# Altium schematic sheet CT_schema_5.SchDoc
size 297 x 173 mm
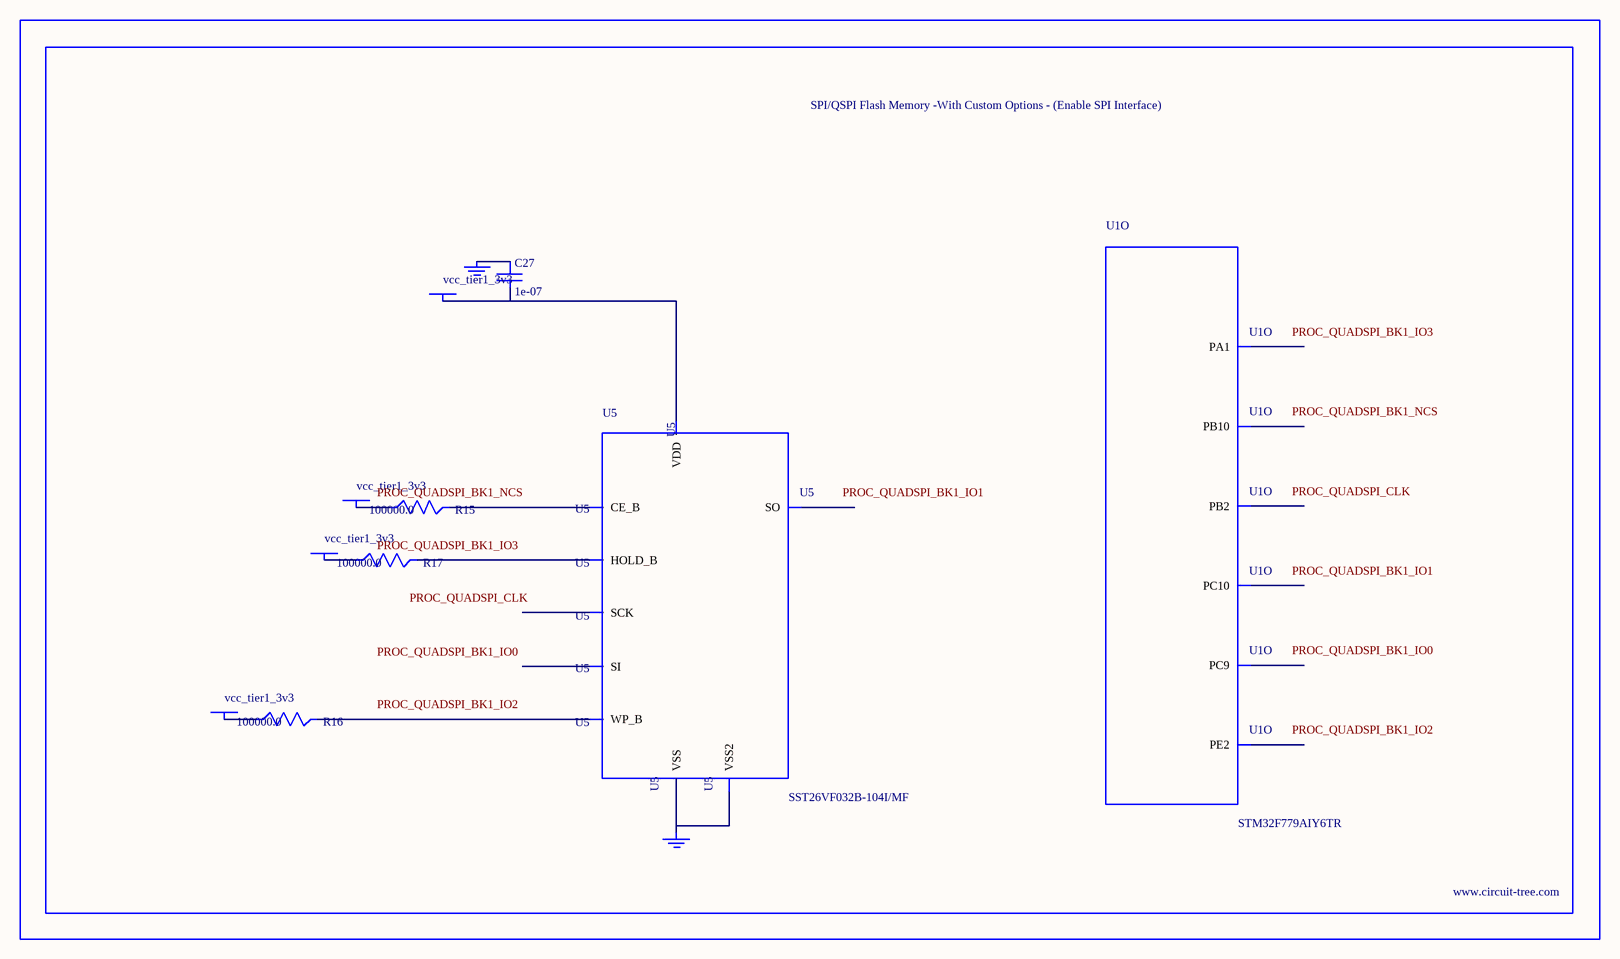
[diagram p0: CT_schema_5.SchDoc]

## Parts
BORDER4  (no value)
C27  1e-07  [C0402]
GND_INSTANCE_4_0  (no value)
GND_INSTANCE_4_1  (no value)
POWER_INSTANCE_4_0  vcc_tier1_3v3
POWER_INSTANCE_4_1  vcc_tier1_3v3
POWER_INSTANCE_4_2  vcc_tier1_3v3
POWER_INSTANCE_4_3  vcc_tier1_3v3
R15  100000.0  [R0603]
R16  100000.0  [R0603]
R17  100000.0  [R0603]
U1  STM32F779AIY6TR  [WLCSP180]  (part O of 15)
U5  SST26VF032B-104I/MF  [WFDN-8]

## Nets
NetC27_1: C27.1 GND_INSTANCE_4_0.0(GND)
NetC27_2: C27.2 POWER_INSTANCE_4_3.0(PWR) U5.8(VDD)
NetGND_INSTANCE_4_1_0: GND_INSTANCE_4_1.0(GND) U5.4(VSS) U5.9(VSS2)
NetPOWER_INSTANCE_4_0_0: POWER_INSTANCE_4_0.0(PWR) R15.1
NetPOWER_INSTANCE_4_1_0: POWER_INSTANCE_4_1.0(PWR) R16.1
NetPOWER_INSTANCE_4_2_0: POWER_INSTANCE_4_2.0(PWR) R17.1
NetR15_2: R15.2 U5.1(CE_B)
NetR16_2: R16.2 U5.3(WP_B)
NetR17_2: R17.2 U5.7(HOLD_B)

Not connected (* = marked no-connect by the designer): U1 B4(PC10) E1(PC9) E10(PE2) J7(PB2) J11(PA1) K5(PB10); U5 2(SO) 5(SI) 6(SCK)

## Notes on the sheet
- Labels drawn without touching a wire or pin: PROC_QUADSPI_BK1_IO0, PROC_QUADSPI_BK1_IO1, PROC_QUADSPI_BK1_IO2, PROC_QUADSPI_BK1_IO3, PROC_QUADSPI_BK1_NCS, PROC_QUADSPI_CLK

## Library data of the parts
BORDER4 = BORDER_PAGE4
C27 = C0402C104K3RACTU
GND_INSTANCE_4_0 GND_INSTANCE_4_1 = GND
POWER_INSTANCE_4_0-POWER_INSTANCE_4_3 = PWR
R15-R17 = RC0603JR-07100KL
